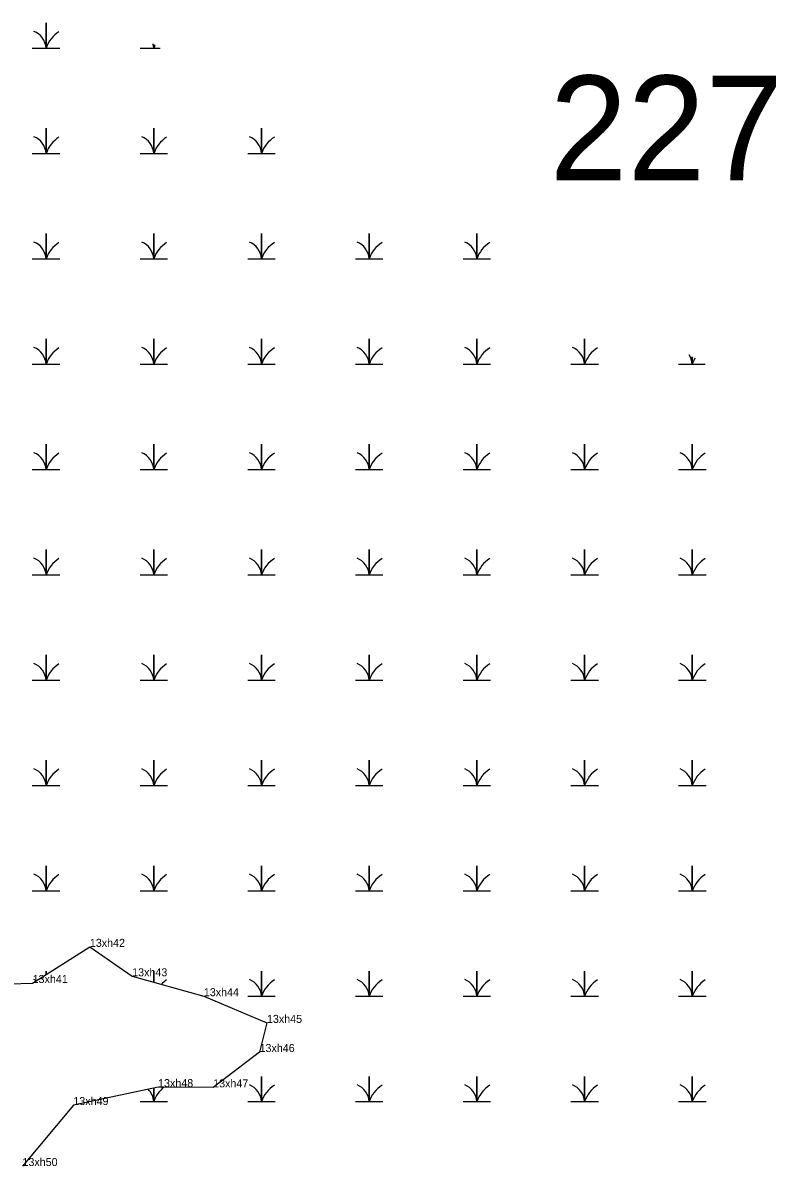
# Model space of a CAD drawing. Extents: x 2072529 to 2268796, y 436423 to 470397.
# Drawn here: x 2248750 to 2249221, y 446231 to 446945 of the extents above; entities that cross this region are included whole.
import ezdxf

# ---------------------------------------------------------------- set-up
doc = ezdxf.new("R2010")
doc.units = 0
for name, color, linetype in [('Default', 7, 'Continuous'), ('Exist Environmental Wetland Boundary', 7, 'Continuous'), ('Exist Environmental Wetland Boundary Cogo Comment', 7, 'Continuous'), ('Exist Environmental Wetland Boundary Cogo Point CELL', 7, 'Continuous'), ('Exist Hydro Swamp or Marsh', 7, 'Continuous')]:
    doc.layers.add(name, color=color, linetype=linetype)

msp = doc.modelspace()

# ---------------------------------------------------------------- linework, layer by layer
at = {"layer": 'Exist Environmental Wetland Boundary'}
msp.add_lwpolyline([(2248713.09, 446344.22), (2248756.47, 446345.67), (2248792.2, 446368.25), (2248818.62, 446349.86), (2248863.37, 446337.42), (2248902.77, 446320.77), (2248898.16, 446302.57), (2248869.21, 446280.49), (2248834.79, 446280.65), (2248781.89, 446269.44), (2248750.12, 446231.37)], dxfattribs=at)
at = {"layer": 'Exist Environmental Wetland Boundary Cogo Point CELL'}
for p, q in [((2248792.2, 446368.25), (2248792.2, 446368.25)), ((2248756.47, 446345.67), (2248756.47, 446345.67)), ((2248818.62, 446349.86), (2248818.62, 446349.86)), ((2248863.37, 446337.42), (2248863.37, 446337.42)), ((2248902.77, 446320.77), (2248902.77, 446320.77)), ((2248898.16, 446302.57), (2248898.16, 446302.57)), ((2248834.79, 446280.65), (2248834.79, 446280.65)), ((2248869.21, 446280.49), (2248869.21, 446280.49)), ((2248781.89, 446269.44), (2248781.89, 446269.44))]:
    msp.add_line(p, q, dxfattribs=at)
at = {"layer": 'Exist Hydro Swamp or Marsh'}
for points in [[(2248756.26, 446929.57), (2248764.86, 446929.57), (2248764.86, 446945.35), (2248764.86, 446929.57), (2248773.47, 446929.57)], [(2248823.51, 446929.57), (2248832.11, 446929.57), (2248832.11, 446931.89)], [(2248832.11, 446931.89), (2248832.11, 446929.57), (2248836.12, 446929.57)], [(2248756.26, 446863.77), (2248764.86, 446863.77), (2248764.86, 446879.55), (2248764.86, 446863.77), (2248773.47, 446863.77)], [(2248823.51, 446863.77), (2248832.11, 446863.77), (2248832.11, 446879.55), (2248832.11, 446863.77), (2248840.72, 446863.77)], [(2248890.76, 446863.77), (2248899.36, 446863.77), (2248899.36, 446879.55), (2248899.36, 446863.77), (2248907.97, 446863.77)], [(2248756.26, 446797.97), (2248764.86, 446797.97), (2248764.86, 446813.75), (2248764.86, 446797.97), (2248773.47, 446797.97)], [(2248823.51, 446797.97), (2248832.11, 446797.97), (2248832.11, 446813.75), (2248832.11, 446797.97), (2248840.72, 446797.97)], [(2248890.76, 446797.97), (2248899.36, 446797.97), (2248899.36, 446813.75), (2248899.36, 446797.97), (2248907.97, 446797.97)], [(2248958.01, 446797.97), (2248966.61, 446797.97), (2248966.61, 446813.75), (2248966.61, 446797.97), (2248975.22, 446797.97)], [(2249025.26, 446797.97), (2249033.86, 446797.97), (2249033.86, 446813.75), (2249033.86, 446797.97), (2249042.47, 446797.97)], [(2248756.26, 446732.17), (2248764.86, 446732.17), (2248764.86, 446747.95), (2248764.86, 446732.17), (2248773.47, 446732.17)], [(2248823.51, 446732.17), (2248832.11, 446732.17), (2248832.11, 446747.95), (2248832.11, 446732.17), (2248840.72, 446732.17)], [(2248890.76, 446732.17), (2248899.36, 446732.17), (2248899.36, 446747.95), (2248899.36, 446732.17), (2248907.97, 446732.17)], [(2248958.01, 446732.17), (2248966.61, 446732.17), (2248966.61, 446747.95), (2248966.61, 446732.17), (2248975.22, 446732.17)], [(2249025.26, 446732.17), (2249033.86, 446732.17), (2249033.86, 446747.95), (2249033.86, 446732.17), (2249042.47, 446732.17)], [(2249092.51, 446732.17), (2249101.11, 446732.17), (2249101.11, 446747.95), (2249101.11, 446732.17), (2249109.72, 446732.17)], [(2249159.76, 446732.17), (2249168.36, 446732.17), (2249168.36, 446736.85)], [(2249168.36, 446736.85), (2249168.36, 446732.17), (2249176.45, 446732.17)], [(2248756.26, 446666.37), (2248764.86, 446666.37), (2248764.86, 446682.15), (2248764.86, 446666.37), (2248773.47, 446666.37)], [(2248823.51, 446666.37), (2248832.11, 446666.37), (2248832.11, 446682.15), (2248832.11, 446666.37), (2248840.72, 446666.37)], [(2248890.76, 446666.37), (2248899.36, 446666.37), (2248899.36, 446682.15), (2248899.36, 446666.37), (2248907.97, 446666.37)], [(2248958.01, 446666.37), (2248966.61, 446666.37), (2248966.61, 446682.15), (2248966.61, 446666.37), (2248975.22, 446666.37)], [(2249025.26, 446666.37), (2249033.86, 446666.37), (2249033.86, 446682.15), (2249033.86, 446666.37), (2249042.47, 446666.37)], [(2249092.51, 446666.37), (2249101.11, 446666.37), (2249101.11, 446682.15), (2249101.11, 446666.37), (2249109.72, 446666.37)], [(2249159.76, 446666.37), (2249168.36, 446666.37), (2249168.36, 446682.15), (2249168.36, 446666.37), (2249176.97, 446666.37)], [(2248756.26, 446600.57), (2248764.86, 446600.57), (2248764.86, 446616.35), (2248764.86, 446600.57), (2248773.47, 446600.57)], [(2248823.51, 446600.57), (2248832.11, 446600.57), (2248832.11, 446616.35), (2248832.11, 446600.57), (2248840.72, 446600.57)], [(2248890.76, 446600.57), (2248899.36, 446600.57), (2248899.36, 446616.35), (2248899.36, 446600.57), (2248907.97, 446600.57)], [(2248958.01, 446600.57), (2248966.61, 446600.57), (2248966.61, 446616.35), (2248966.61, 446600.57), (2248975.22, 446600.57)], [(2249025.26, 446600.57), (2249033.86, 446600.57), (2249033.86, 446616.35), (2249033.86, 446600.57), (2249042.47, 446600.57)], [(2249092.51, 446600.57), (2249101.11, 446600.57), (2249101.11, 446616.35), (2249101.11, 446600.57), (2249109.72, 446600.57)], [(2249159.76, 446600.57), (2249168.36, 446600.57), (2249168.36, 446616.35), (2249168.36, 446600.57), (2249176.97, 446600.57)], [(2248756.26, 446534.77), (2248764.86, 446534.77), (2248764.86, 446550.55), (2248764.86, 446534.77), (2248773.47, 446534.77)], [(2248823.51, 446534.77), (2248832.11, 446534.77), (2248832.11, 446550.55), (2248832.11, 446534.77), (2248840.72, 446534.77)], [(2248890.76, 446534.77), (2248899.36, 446534.77), (2248899.36, 446550.55), (2248899.36, 446534.77), (2248907.97, 446534.77)], [(2248958.01, 446534.77), (2248966.61, 446534.77), (2248966.61, 446550.55), (2248966.61, 446534.77), (2248975.22, 446534.77)], [(2249025.26, 446534.77), (2249033.86, 446534.77), (2249033.86, 446550.55), (2249033.86, 446534.77), (2249042.47, 446534.77)], [(2249092.51, 446534.77), (2249101.11, 446534.77), (2249101.11, 446550.55), (2249101.11, 446534.77), (2249109.72, 446534.77)], [(2249159.76, 446534.77), (2249168.36, 446534.77), (2249168.36, 446550.55), (2249168.36, 446534.77), (2249176.97, 446534.77)], [(2248756.26, 446468.97), (2248764.86, 446468.97), (2248764.86, 446484.75), (2248764.86, 446468.97), (2248773.47, 446468.97)], [(2248823.51, 446468.97), (2248832.11, 446468.97), (2248832.11, 446484.75), (2248832.11, 446468.97), (2248840.72, 446468.97)], [(2248890.76, 446468.97), (2248899.36, 446468.97), (2248899.36, 446484.75), (2248899.36, 446468.97), (2248907.97, 446468.97)], [(2248958.01, 446468.97), (2248966.61, 446468.97), (2248966.61, 446484.75), (2248966.61, 446468.97), (2248975.22, 446468.97)], [(2249025.26, 446468.97), (2249033.86, 446468.97), (2249033.86, 446484.75), (2249033.86, 446468.97), (2249042.47, 446468.97)], [(2249092.51, 446468.97), (2249101.11, 446468.97), (2249101.11, 446484.75), (2249101.11, 446468.97), (2249109.72, 446468.97)], [(2249159.76, 446468.97), (2249168.36, 446468.97), (2249168.36, 446484.75), (2249168.36, 446468.97), (2249176.97, 446468.97)], [(2248756.26, 446403.17), (2248764.86, 446403.17), (2248764.86, 446418.95), (2248764.86, 446403.17), (2248773.47, 446403.17)], [(2248823.51, 446403.17), (2248832.11, 446403.17), (2248832.11, 446418.95), (2248832.11, 446403.17), (2248840.72, 446403.17)], [(2248890.76, 446403.17), (2248899.36, 446403.17), (2248899.36, 446418.95), (2248899.36, 446403.17), (2248907.97, 446403.17)], [(2248958.01, 446403.17), (2248966.61, 446403.17), (2248966.61, 446418.95), (2248966.61, 446403.17), (2248975.22, 446403.17)], [(2249025.26, 446403.17), (2249033.86, 446403.17), (2249033.86, 446418.95), (2249033.86, 446403.17), (2249042.47, 446403.17)], [(2249092.51, 446403.17), (2249101.11, 446403.17), (2249101.11, 446418.95), (2249101.11, 446403.17), (2249109.72, 446403.17)], [(2249159.76, 446403.17), (2249168.36, 446403.17), (2249168.36, 446418.95), (2249168.36, 446403.17), (2249176.97, 446403.17)], [(2248764.86, 446350.98), (2248764.86, 446353.15), (2248764.86, 446350.98)], [(2248832.11, 446346.11), (2248832.11, 446353.15), (2248832.11, 446346.11)], [(2248890.76, 446337.37), (2248899.36, 446337.37), (2248899.36, 446353.15), (2248899.36, 446337.37), (2248907.97, 446337.37)], [(2248958.01, 446337.37), (2248966.61, 446337.37), (2248966.61, 446353.15), (2248966.61, 446337.37), (2248975.22, 446337.37)], [(2249025.26, 446337.37), (2249033.86, 446337.37), (2249033.86, 446353.15), (2249033.86, 446337.37), (2249042.47, 446337.37)], [(2249092.51, 446337.37), (2249101.11, 446337.37), (2249101.11, 446353.15), (2249101.11, 446337.37), (2249109.72, 446337.37)], [(2249159.76, 446337.37), (2249168.36, 446337.37), (2249168.36, 446353.15), (2249168.36, 446337.37), (2249176.97, 446337.37)], [(2248890.76, 446271.57), (2248899.36, 446271.57), (2248899.36, 446287.35), (2248899.36, 446271.57), (2248907.97, 446271.57)], [(2248958.01, 446271.57), (2248966.61, 446271.57), (2248966.61, 446287.35), (2248966.61, 446271.57), (2248975.22, 446271.57)], [(2249025.26, 446271.57), (2249033.86, 446271.57), (2249033.86, 446287.35), (2249033.86, 446271.57), (2249042.47, 446271.57)], [(2249092.51, 446271.57), (2249101.11, 446271.57), (2249101.11, 446287.35), (2249101.11, 446271.57), (2249109.72, 446271.57)], [(2249159.76, 446271.57), (2249168.36, 446271.57), (2249168.36, 446287.35), (2249168.36, 446271.57), (2249176.97, 446271.57)], [(2248823.51, 446271.57), (2248832.11, 446271.57), (2248832.11, 446280.09)], [(2248832.11, 446280.09), (2248832.11, 446271.57), (2248840.72, 446271.57)]]:
    msp.add_lwpolyline(points, dxfattribs=at)
for centre, radius, start, end in [((2248752.6, 446928.68), 12.3, 4.14034, 67.53497), ((2248783.11, 446923.5), 19.22, 122.12745, 161.62219), ((2248819.85, 446928.68), 12.3, 4.14034, 16.44871), ((2248850.36, 446923.5), 19.22, 155.56501, 161.62219), ((2248752.6, 446862.88), 12.3, 4.14034, 67.53497), ((2248783.11, 446857.7), 19.22, 122.12745, 161.62219), ((2248819.85, 446862.88), 12.3, 4.14034, 67.53497), ((2248850.36, 446857.7), 19.22, 122.12745, 161.62219), ((2248887.1, 446862.88), 12.3, 4.14034, 67.53497), ((2248917.61, 446857.7), 19.22, 122.12745, 161.62219), ((2248752.6, 446797.08), 12.3, 4.14034, 67.53497), ((2248783.11, 446791.9), 19.22, 122.12745, 161.62219), ((2248819.85, 446797.08), 12.3, 4.14034, 67.53497), ((2248850.36, 446791.9), 19.22, 122.12745, 161.62219), ((2248887.1, 446797.08), 12.3, 4.14034, 67.53497), ((2248917.61, 446791.9), 19.22, 122.12745, 161.62219), ((2248954.35, 446797.08), 12.3, 4.14034, 67.53497), ((2248984.86, 446791.9), 19.22, 122.12745, 161.62219), ((2249021.6, 446797.08), 12.3, 4.14034, 67.53497), ((2249052.11, 446791.9), 19.22, 122.12745, 161.62219), ((2248752.6, 446731.28), 12.3, 4.14034, 67.53497), ((2248783.11, 446726.1), 19.22, 122.12745, 161.62219), ((2248819.85, 446731.28), 12.3, 4.14034, 67.53497), ((2248850.36, 446726.1), 19.22, 122.12745, 161.62219), ((2248887.1, 446731.28), 12.3, 4.14034, 67.53497), ((2248917.61, 446726.1), 19.22, 122.12745, 161.62219), ((2248954.35, 446731.28), 12.3, 4.14034, 67.53497), ((2248984.86, 446726.1), 19.22, 122.12745, 161.62219), ((2249021.6, 446731.28), 12.3, 4.14034, 67.53497), ((2249052.11, 446726.1), 19.22, 122.12745, 161.62219), ((2249088.85, 446731.28), 12.3, 4.14034, 67.53497), ((2249119.36, 446726.1), 19.22, 122.12745, 161.62219), ((2249156.1, 446731.28), 12.3, 4.14034, 33.08524), ((2249186.61, 446726.1), 19.22, 149.45416, 161.62219), ((2248752.6, 446665.48), 12.3, 4.14034, 67.53497), ((2248783.11, 446660.3), 19.22, 122.12745, 161.62219), ((2248819.85, 446665.48), 12.3, 4.14034, 67.53497), ((2248850.36, 446660.3), 19.22, 122.12745, 161.62219), ((2248887.1, 446665.48), 12.3, 4.14034, 67.53497), ((2248917.61, 446660.3), 19.22, 122.12745, 161.62219), ((2248954.35, 446665.48), 12.3, 4.14034, 67.53497), ((2248984.86, 446660.3), 19.22, 122.12745, 161.62219), ((2249021.6, 446665.48), 12.3, 4.14034, 67.53497), ((2249052.11, 446660.3), 19.22, 122.12745, 161.62219), ((2249088.85, 446665.48), 12.3, 4.14034, 67.53497), ((2249119.36, 446660.3), 19.22, 122.12745, 161.62219), ((2249156.1, 446665.48), 12.3, 4.14034, 67.53497), ((2249186.61, 446660.3), 19.22, 122.12745, 161.62219), ((2248752.6, 446599.68), 12.3, 4.14034, 67.53497), ((2248783.11, 446594.5), 19.22, 122.12745, 161.62219), ((2248819.85, 446599.68), 12.3, 4.14034, 67.53497), ((2248850.36, 446594.5), 19.22, 122.12745, 161.62219), ((2248887.1, 446599.68), 12.3, 4.14034, 67.53497), ((2248917.61, 446594.5), 19.22, 122.12745, 161.62219), ((2248954.35, 446599.68), 12.3, 4.14034, 67.53497), ((2248984.86, 446594.5), 19.22, 122.12745, 161.62219), ((2249021.6, 446599.68), 12.3, 4.14034, 67.53497), ((2249052.11, 446594.5), 19.22, 122.12745, 161.62219), ((2249088.85, 446599.68), 12.3, 4.14034, 67.53497), ((2249119.36, 446594.5), 19.22, 122.12745, 161.62219), ((2249156.1, 446599.68), 12.3, 4.14034, 67.53497), ((2249186.61, 446594.5), 19.22, 122.12745, 161.62219), ((2248752.6, 446533.88), 12.3, 4.14034, 67.53497), ((2248783.11, 446528.7), 19.22, 122.12745, 161.62219), ((2248819.85, 446533.88), 12.3, 4.14034, 67.53497), ((2248850.36, 446528.7), 19.22, 122.12745, 161.62219), ((2248887.1, 446533.88), 12.3, 4.14034, 67.53497), ((2248917.61, 446528.7), 19.22, 122.12745, 161.62219), ((2248954.35, 446533.88), 12.3, 4.14034, 67.53497), ((2248984.86, 446528.7), 19.22, 122.12745, 161.62219), ((2249021.6, 446533.88), 12.3, 4.14034, 67.53497), ((2249052.11, 446528.7), 19.22, 122.12745, 161.62219), ((2249088.85, 446533.88), 12.3, 4.14034, 67.53497), ((2249119.36, 446528.7), 19.22, 122.12745, 161.62219), ((2249156.1, 446533.88), 12.3, 4.14034, 67.53497), ((2249186.61, 446528.7), 19.22, 122.12745, 161.62219), ((2248752.6, 446468.08), 12.3, 4.14034, 67.53497), ((2248783.11, 446462.9), 19.22, 122.12745, 161.62219), ((2248819.85, 446468.08), 12.3, 4.14034, 67.53497), ((2248850.36, 446462.9), 19.22, 122.12745, 161.62219), ((2248887.1, 446468.08), 12.3, 4.14034, 67.53497), ((2248917.61, 446462.9), 19.22, 122.12745, 161.62219), ((2248954.35, 446468.08), 12.3, 4.14034, 67.53497), ((2248984.86, 446462.9), 19.22, 122.12745, 161.62219), ((2249021.6, 446468.08), 12.3, 4.14034, 67.53497), ((2249052.11, 446462.9), 19.22, 122.12745, 161.62219), ((2249088.85, 446468.08), 12.3, 4.14034, 67.53497), ((2249119.36, 446462.9), 19.22, 122.12745, 161.62219), ((2249156.1, 446468.08), 12.3, 4.14034, 67.53497), ((2249186.61, 446462.9), 19.22, 122.12745, 161.62219), ((2248752.6, 446402.28), 12.3, 4.14034, 67.53497), ((2248783.11, 446397.1), 19.22, 122.12745, 161.62219), ((2248819.85, 446402.28), 12.3, 4.14034, 67.53497), ((2248850.36, 446397.1), 19.22, 122.12745, 161.62219), ((2248887.1, 446402.28), 12.3, 4.14034, 67.53497), ((2248917.61, 446397.1), 19.22, 122.12745, 161.62219), ((2248954.35, 446402.28), 12.3, 4.14034, 67.53497), ((2248984.86, 446397.1), 19.22, 122.12745, 161.62219), ((2249021.6, 446402.28), 12.3, 4.14034, 67.53497), ((2249052.11, 446397.1), 19.22, 122.12745, 161.62219), ((2249088.85, 446402.28), 12.3, 4.14034, 67.53497), ((2249119.36, 446397.1), 19.22, 122.12745, 161.62219), ((2249156.1, 446402.28), 12.3, 4.14034, 67.53497), ((2249186.61, 446397.1), 19.22, 122.12745, 161.62219), ((2248752.6, 446336.48), 12.3, 59.921, 67.53497), ((2248850.36, 446331.3), 19.22, 122.12745, 135.26583), ((2248887.1, 446336.48), 12.3, 4.14034, 67.53497), ((2248917.61, 446331.3), 19.22, 122.12745, 161.62219), ((2248954.35, 446336.48), 12.3, 4.14034, 67.53497), ((2248984.86, 446331.3), 19.22, 122.12745, 161.62219), ((2249021.6, 446336.48), 12.3, 4.14034, 67.53497), ((2249052.11, 446331.3), 19.22, 122.12745, 161.62219), ((2249088.85, 446336.48), 12.3, 4.14034, 67.53497), ((2249119.36, 446331.3), 19.22, 122.12745, 161.62219), ((2249156.1, 446336.48), 12.3, 4.14034, 67.53497), ((2249186.61, 446331.3), 19.22, 122.12745, 161.62219), ((2248850.36, 446265.5), 19.22, 128.0854, 161.62219), ((2248887.1, 446270.68), 12.3, 4.14034, 67.53497), ((2248917.61, 446265.5), 19.22, 122.12745, 161.62219), ((2248954.35, 446270.68), 12.3, 4.14034, 67.53497), ((2248984.86, 446265.5), 19.22, 122.12745, 161.62219), ((2249021.6, 446270.68), 12.3, 4.14034, 67.53497), ((2249052.11, 446265.5), 19.22, 122.12745, 161.62219), ((2249088.85, 446270.68), 12.3, 4.14034, 67.53497), ((2249119.36, 446265.5), 19.22, 122.12745, 161.62219), ((2249156.1, 446270.68), 12.3, 4.14034, 67.53497), ((2249186.61, 446265.5), 19.22, 122.12745, 161.62219), ((2248819.85, 446270.68), 12.3, 4.14034, 44.7549)]:
    msp.add_arc(centre, radius, start, end, dxfattribs=at)

# ---------------------------------------------------------------- texts
at = {"layer": 'Default'}
msp.add_text('227', height=65.34, dxfattribs=at).set_placement((2249079.33, 446847.05))
at = {"layer": 'Exist Environmental Wetland Boundary Cogo Comment'}
for s, p in [('13xh42', (2248792.2, 446368.25)), ('13xh43', (2248818.62, 446349.86)), ('13xh41', (2248756.47, 446345.67)), ('13xh44', (2248863.37, 446337.42)), ('13xh45', (2248902.77, 446320.77)), ('13xh46', (2248898.16, 446302.57)), ('13xh48', (2248834.79, 446280.65)), ('13xh47', (2248869.21, 446280.49)), ('13xh49', (2248781.89, 446269.44)), ('13xh50', (2248750.12, 446231.37))]:
    msp.add_text(s, height=5, dxfattribs=at).set_placement(p)

doc.saveas('drawing.dxf')
